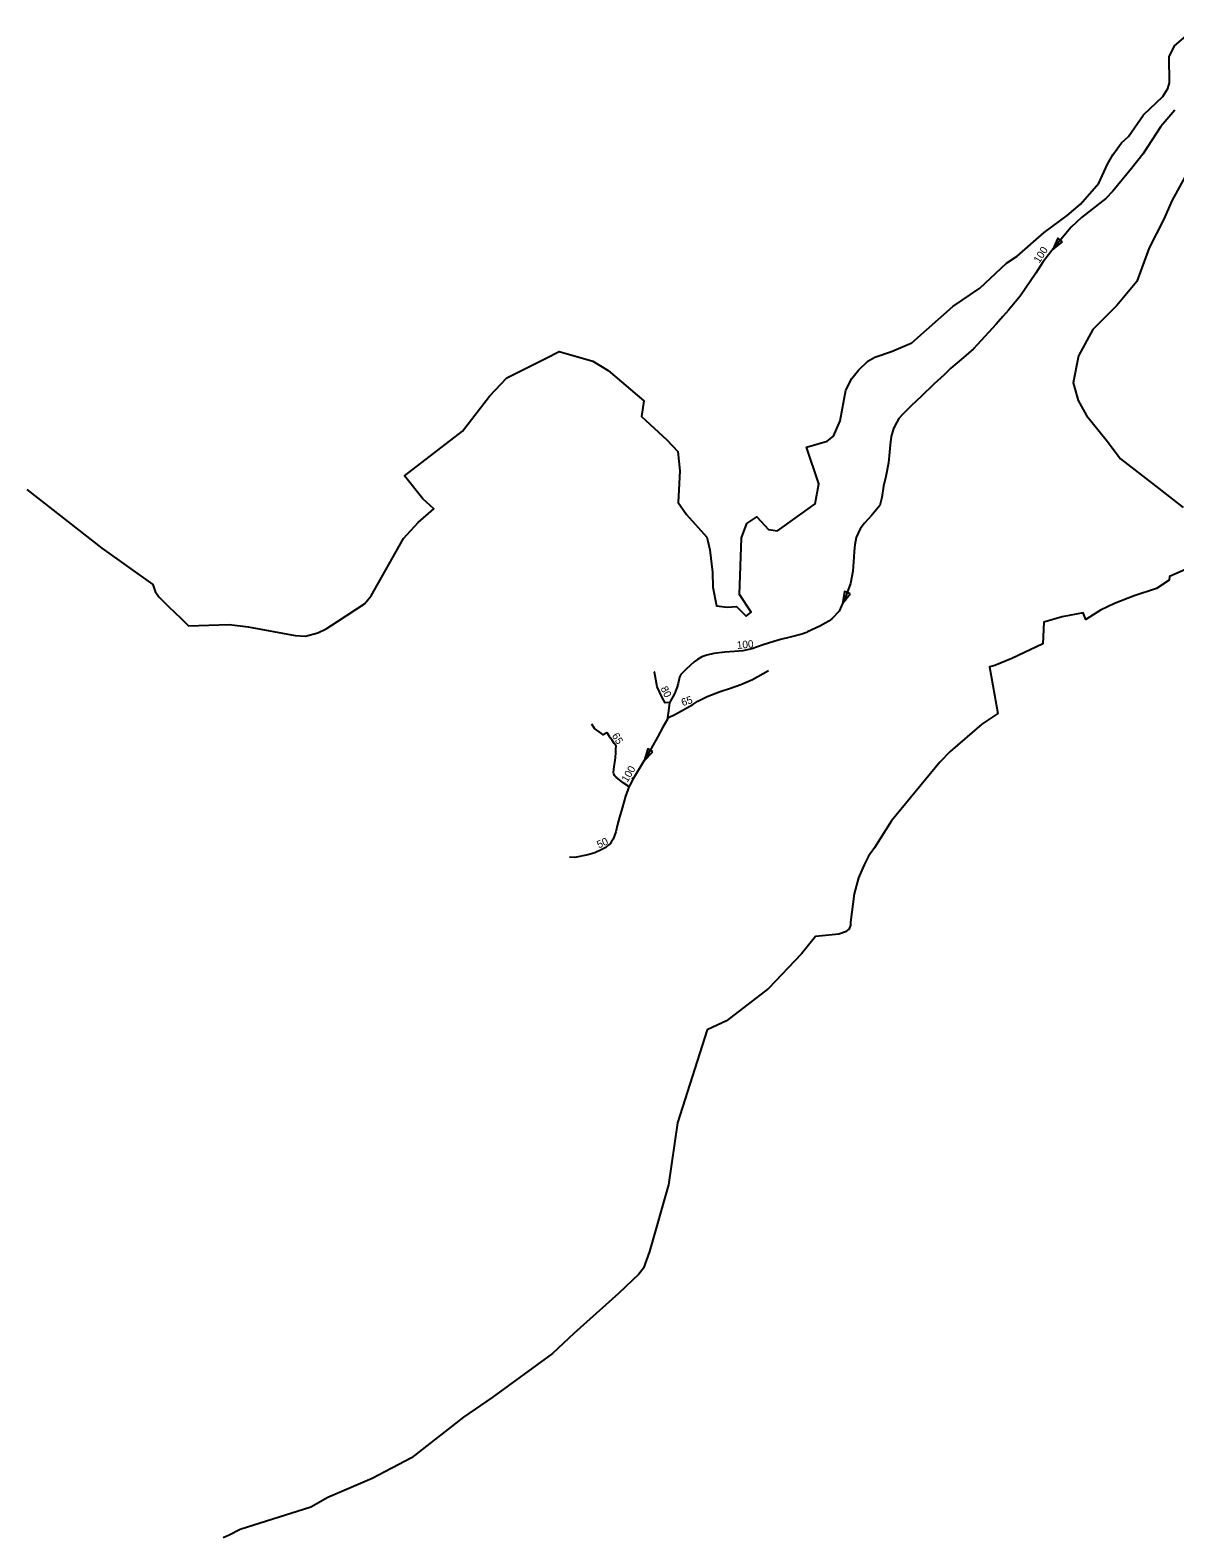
# Model space of a CAD drawing. Extents: x -547132 to -534149, y -1095664 to -1090118.
# Drawn here: x -545605 to -544078, y -1095664 to -1093653 of the extents above; entities that cross this region are included whole.
import ezdxf

# ---------------------------------------------------------------- set-up
doc = ezdxf.new("R2010")
doc.units = 0
doc.layers.add('Vrstva 3', color=7, linetype='Continuous')
doc.layers.add('Vrstva 54', color=7, linetype='Continuous')

msp = doc.modelspace()

# ---------------------------------------------------------------- linework, layer by layer
at = {"layer": 'Vrstva 3'}
for p, q in [((-544346.8, -1094078.5), (-544347, -1094078.4)), ((-544346.8, -1094078.5), (-544347, -1094078.4)), ((-544471.6, -1094287.4), (-544471.4, -1094287.4)), ((-544471.6, -1094287.4), (-544471.4, -1094287.4)), ((-544516.6, -1094407.1), (-544525.9, -1094428.4)), ((-544516.6, -1094407.1), (-544525.9, -1094428.4)), ((-544800.4, -1094652), (-544802.4, -1094650.8)), ((-544800.4, -1094652), (-544802.4, -1094650.8))]:
    msp.add_line(p, q, dxfattribs=at)
for points in [[(-544078.1, -1093759.8), (-544096.7, -1093782), (-544120.8, -1093818.9), (-544135.7, -1093837.7), (-544160.8, -1093868.2), (-544170, -1093877.9), (-544188.5, -1093891.9), (-544202.8, -1093903.2), (-544216.3, -1093916.1), (-544238.9, -1093943.2), (-544254, -1093962.7), (-544263.4, -1093977.3), (-544284.6, -1094008), (-544299.8, -1094026.6), (-544307.5, -1094035.3), (-544316.2, -1094045.5), (-544341.9, -1094072.9), (-544346.8, -1094078.5)], [(-544078.1, -1093759.8), (-544096.7, -1093782), (-544120.8, -1093818.9), (-544135.7, -1093837.7), (-544160.8, -1093868.2), (-544170, -1093877.9), (-544188.5, -1093891.9), (-544202.8, -1093903.2), (-544216.3, -1093916.1), (-544238.9, -1093943.2), (-544254, -1093962.7), (-544263.4, -1093977.3), (-544284.6, -1094008), (-544299.8, -1094026.6), (-544307.5, -1094035.3), (-544316.2, -1094045.5), (-544341.9, -1094072.9), (-544346.8, -1094078.5)], [(-544346.8, -1094078.5), (-544360, -1094090.1), (-544376.9, -1094104), (-544385.9, -1094112.9), (-544399.2, -1094125.1), (-544416.6, -1094141.7), (-544429.5, -1094154), (-544440.9, -1094165.4), (-544446.1, -1094171.2), (-544449, -1094176), (-544453.2, -1094184.5), (-544456.3, -1094195.3), (-544457.9, -1094206.5), (-544458.8, -1094216.1), (-544460.1, -1094230.3), (-544463.6, -1094248.7), (-544466.5, -1094261.6), (-544469, -1094276.7), (-544471.6, -1094287.4)], [(-544346.8, -1094078.5), (-544360, -1094090.1), (-544376.9, -1094104), (-544385.9, -1094112.9), (-544399.2, -1094125.1), (-544416.6, -1094141.7), (-544429.5, -1094154), (-544440.9, -1094165.4), (-544446.1, -1094171.2), (-544449, -1094176), (-544453.2, -1094184.5), (-544456.3, -1094195.3), (-544457.9, -1094206.5), (-544458.8, -1094216.1), (-544460.1, -1094230.3), (-544463.6, -1094248.7), (-544466.5, -1094261.6), (-544469, -1094276.7), (-544471.6, -1094287.4)], [(-544471.6, -1094287.4), (-544482.4, -1094300.3), (-544492.2, -1094310.9), (-544498, -1094318.5), (-544503, -1094330.1), (-544504.8, -1094339.7), (-544505.8, -1094348.2)], [(-544471.6, -1094287.4), (-544482.4, -1094300.3), (-544492.2, -1094310.9), (-544498, -1094318.5), (-544503, -1094330.1), (-544504.8, -1094339.7), (-544505.8, -1094348.2)], [(-544505.8, -1094348.2), (-544506.3, -1094356), (-544507.5, -1094374.7), (-544510.9, -1094391.5), (-544516.6, -1094407.1)], [(-544505.8, -1094348.2), (-544506.3, -1094356), (-544507.5, -1094374.7), (-544510.9, -1094391.5), (-544516.6, -1094407.1)], [(-544525.9, -1094428.4), (-544535.2, -1094438.1), (-544539.6, -1094441.5), (-544551.5, -1094448.4), (-544567.9, -1094455.9), (-544569.6, -1094456.6), (-544575.6, -1094458.8), (-544591, -1094463.1), (-544604, -1094465.9), (-544612.9, -1094468.6), (-544627.3, -1094473.1), (-544642.3, -1094478.5), (-544654.5, -1094481.1), (-544665.5, -1094482.1), (-544678.4, -1094482.8), (-544692.9, -1094484.9), (-544702.5, -1094487), (-544708.9, -1094489.3), (-544715, -1094492.6), (-544719.3, -1094495.7), (-544730.1, -1094505.5), (-544737.2, -1094512.7), (-544738.7, -1094516.4), (-544740.7, -1094524.8), (-544742.3, -1094530.6), (-544745.4, -1094538.3), (-544751.7, -1094549.5), (-544752, -1094550.3)], [(-544525.9, -1094428.4), (-544535.2, -1094438.1), (-544539.6, -1094441.5), (-544551.5, -1094448.4), (-544567.9, -1094455.9), (-544569.6, -1094456.6), (-544575.6, -1094458.8), (-544591, -1094463.1), (-544604, -1094465.9), (-544612.9, -1094468.6), (-544627.3, -1094473.1), (-544642.3, -1094478.5), (-544654.5, -1094481.1), (-544665.5, -1094482.1), (-544678.4, -1094482.8), (-544692.9, -1094484.9), (-544702.5, -1094487), (-544708.9, -1094489.3), (-544715, -1094492.6), (-544719.3, -1094495.7), (-544730.1, -1094505.5), (-544737.2, -1094512.7), (-544738.7, -1094516.4), (-544740.7, -1094524.8), (-544742.3, -1094530.6), (-544745.4, -1094538.3), (-544751.7, -1094549.5), (-544752, -1094550.3)], [(-544752, -1094550.3), (-544752.3, -1094550.2), (-544758.1, -1094550.7), (-544761.8, -1094543.3), (-544768.8, -1094529.1), (-544772.1, -1094509.6), (-544772, -1094509.4), (-544772.4, -1094509.3), (-544772.7, -1094509.3)], [(-544752, -1094550.3), (-544752.3, -1094550.2), (-544758.1, -1094550.7), (-544761.8, -1094543.3), (-544768.8, -1094529.1), (-544772.1, -1094509.6), (-544772, -1094509.4), (-544772.4, -1094509.3), (-544772.7, -1094509.3)], [(-544754.6, -1094570.7), (-544754.2, -1094570.7), (-544744.1, -1094565.7), (-544736.3, -1094561.2), (-544721.1, -1094552.8), (-544714.2, -1094548.1), (-544701.7, -1094542.1), (-544684.6, -1094535.5), (-544670.8, -1094530.8), (-544656.8, -1094526), (-544641.6, -1094519.4), (-544619.9, -1094507.4)], [(-544754.6, -1094570.7), (-544754.2, -1094570.7), (-544744.1, -1094565.7), (-544736.3, -1094561.2), (-544721.1, -1094552.8), (-544714.2, -1094548.1), (-544701.7, -1094542.1), (-544684.6, -1094535.5), (-544670.8, -1094530.8), (-544656.8, -1094526), (-544641.6, -1094519.4), (-544619.9, -1094507.4)], [(-544752, -1094550.3), (-544753.8, -1094564.4), (-544754.6, -1094570.7)], [(-544752, -1094550.3), (-544753.8, -1094564.4), (-544754.6, -1094570.7)], [(-544754.6, -1094570.7), (-544754.8, -1094572.2), (-544760.9, -1094583), (-544768, -1094596.3), (-544780.4, -1094618.6), (-544800.4, -1094652), (-544805.1, -1094660.5), (-544805.9, -1094662.3)], [(-544754.6, -1094570.7), (-544754.8, -1094572.2), (-544760.9, -1094583), (-544768, -1094596.3), (-544780.4, -1094618.6), (-544800.4, -1094652), (-544805.1, -1094660.5), (-544805.9, -1094662.3)], [(-544835.5, -1094590.4), (-544835.6, -1094590.5), (-544836.8, -1094591.1), (-544840.7, -1094593), (-544843, -1094591.2), (-544852.1, -1094584.6), (-544855.8, -1094579)], [(-544835.5, -1094590.4), (-544835.6, -1094590.5), (-544836.8, -1094591.1), (-544840.7, -1094593), (-544843, -1094591.2), (-544852.1, -1094584.6), (-544855.8, -1094579)], [(-544836.1, -1094589.7), (-544835.9, -1094589.9), (-544835.5, -1094590.4)], [(-544836.1, -1094589.7), (-544835.9, -1094589.9), (-544835.5, -1094590.4)], [(-544805.9, -1094662.3), (-544806.4, -1094662), (-544814, -1094657.2), (-544823.5, -1094649.7), (-544824.2, -1094649), (-544825.5, -1094647.2), (-544826.4, -1094645), (-544827, -1094643.6), (-544826.2, -1094639.1), (-544824.2, -1094623.7), (-544823.8, -1094616.9), (-544823.6, -1094612.7), (-544823.1, -1094608), (-544825.8, -1094604.6), (-544828.7, -1094600.3), (-544831.1, -1094597.1), (-544832.2, -1094595.3), (-544835.5, -1094590.4)], [(-544805.9, -1094662.3), (-544806.4, -1094662), (-544814, -1094657.2), (-544823.5, -1094649.7), (-544824.2, -1094649), (-544825.5, -1094647.2), (-544826.4, -1094645), (-544827, -1094643.6), (-544826.2, -1094639.1), (-544824.2, -1094623.7), (-544823.8, -1094616.9), (-544823.6, -1094612.7), (-544823.1, -1094608), (-544825.8, -1094604.6), (-544828.7, -1094600.3), (-544831.1, -1094597.1), (-544832.2, -1094595.3), (-544835.5, -1094590.4)], [(-544805.9, -1094662.3), (-544806.7, -1094663.9), (-544807.8, -1094666.6), (-544810.7, -1094674.9), (-544815.4, -1094690.8), (-544818.7, -1094703.2), (-544821.5, -1094712.8), (-544823.8, -1094722.7), (-544827.4, -1094732.3), (-544829.4, -1094735.4), (-544831.5, -1094738.5), (-544833.1, -1094740.1), (-544837.2, -1094743.5), (-544842.2, -1094746.2), (-544851.9, -1094750.4), (-544860.9, -1094753.2), (-544878.6, -1094756.7), (-544885.4, -1094756.5)], [(-544805.9, -1094662.3), (-544806.7, -1094663.9), (-544807.8, -1094666.6), (-544810.7, -1094674.9), (-544815.4, -1094690.8), (-544818.7, -1094703.2), (-544821.5, -1094712.8), (-544823.8, -1094722.7), (-544827.4, -1094732.3), (-544829.4, -1094735.4), (-544831.5, -1094738.5), (-544833.1, -1094740.1), (-544837.2, -1094743.5), (-544842.2, -1094746.2), (-544851.9, -1094750.4), (-544860.9, -1094753.2), (-544878.6, -1094756.7), (-544885.4, -1094756.5)]]:
    msp.add_lwpolyline(points, dxfattribs=at)
for points in [[(-544228, -1093935.5), (-544234.3, -1093930.6), (-544240.9, -1093945.7)], [(-544511.3, -1094405), (-544518.7, -1094401.8), (-544521.4, -1094418.1)], [(-544774.2, -1094616), (-544781.1, -1094611.9), (-544785.9, -1094627.7)]]:
    msp.add_lwpolyline(points, close=True, dxfattribs=at)
at = {"layer": 'Vrstva 54'}
for points in [[(-545609.5, -1094266.1), (-545509.4, -1094344.2), (-545441.3, -1094392.8), (-545438, -1094402.1), (-545433.4, -1094409), (-545420.6, -1094422.2), (-545403.6, -1094437.8), (-545393.6, -1094448), (-545339.3, -1094446.2), (-545314, -1094449.3), (-545251.5, -1094460.8), (-545237.9, -1094461.5), (-545221.4, -1094457.1), (-545210.2, -1094451.7), (-545195.1, -1094442.1), (-545159.2, -1094418.5), (-545150.3, -1094407.8), (-545106.9, -1094331.4), (-545087.6, -1094309.9), (-545066.3, -1094291.6), (-545081.1, -1094278.2), (-545105.6, -1094247.8), (-545028.1, -1094188.3), (-544992.1, -1094141.6), (-544969.3, -1094117.1), (-544916.7, -1094090.8), (-544899.3, -1094081.7), (-544854.6, -1094094.9), (-544833.8, -1094107.4), (-544786.2, -1094147.9), (-544789.5, -1094168.8), (-544755.7, -1094199.7), (-544741.2, -1094215.5), (-544738.5, -1094241), (-544740.6, -1094283.1), (-544729.6, -1094299.3), (-544702.4, -1094329.6), (-544701.1, -1094335), (-544698.4, -1094346.5), (-544694.8, -1094376.4), (-544694.5, -1094396.1), (-544689.5, -1094421.2), (-544675.4, -1094422.7), (-544662.8, -1094421.8), (-544649.8, -1094435), (-544643.1, -1094429.5), (-544658.9, -1094406.1), (-544656.3, -1094330.6), (-544648.9, -1094311.4), (-544635.7, -1094302.4), (-544620.3, -1094319.2), (-544608.3, -1094321), (-544557.7, -1094284.9), (-544552.9, -1094258.5), (-544569.2, -1094209.5), (-544541.9, -1094201.7), (-544533.3, -1094194.7), (-544524.5, -1094174.4), (-544517.1, -1094133.3), (-544509.1, -1094118.1), (-544500.2, -1094106.9), (-544487.4, -1094094.9), (-544478.2, -1094089.3), (-544456.1, -1094082), (-544429, -1094070.3), (-544374.2, -1094022.1), (-544338.2, -1093997.4), (-544302.7, -1093964), (-544288.3, -1093954.6), (-544252.6, -1093923), (-544221.5, -1093900.4), (-544203.8, -1093885.2), (-544179.6, -1093857.2), (-544167.7, -1093832.1), (-544160.9, -1093819.6), (-544149.2, -1093803.4), (-544140.1, -1093795.1), (-544120, -1093766.2), (-544094.3, -1093741.6), (-544087.4, -1093731.2), (-544085.3, -1093723.6), (-544085.5, -1093688.7), (-544078.6, -1093674), (-544054.1, -1093653.3)], [(-544064.2, -1093848.7), (-544082.3, -1093880.9), (-544092.7, -1093905.4), (-544112.5, -1093943.8), (-544128.9, -1093988.7), (-544155.5, -1094020.6), (-544187.3, -1094052.4), (-544206.6, -1094087.7), (-544213.7, -1094123.8), (-544207.2, -1094147.3), (-544196, -1094167.2), (-544169.8, -1094199.5), (-544150.7, -1094224.9), (-544107.3, -1094258.3), (-544067.1, -1094289.8)], [(-544056.6, -1094369.4), (-544085.4, -1094381.8), (-544085.8, -1094386.7), (-544102.4, -1094397.9), (-544132.2, -1094407.6), (-544158.6, -1094417.9), (-544177.1, -1094426.9), (-544196.7, -1094439.5), (-544200.4, -1094430.6), (-544228.4, -1094436), (-544252.8, -1094442.8), (-544254.3, -1094471.8), (-544295.6, -1094491.4), (-544318.2, -1094500.5), (-544325.4, -1094502.6), (-544314.4, -1094564.9), (-544335.7, -1094579.1), (-544377.6, -1094615.3), (-544391.6, -1094629.7), (-544456.2, -1094708.1), (-544478.9, -1094743.7), (-544486.6, -1094755.1), (-544492.5, -1094766.5), (-544500.2, -1094783.8), (-544505.8, -1094805.1), (-544510.7, -1094843.1), (-544510.9, -1094847.2), (-544512.5, -1094852), (-544517.6, -1094856.1), (-544526.3, -1094859), (-544557.6, -1094862.1), (-544575.9, -1094885.2), (-544620, -1094931.4), (-544676.1, -1094974.6), (-544701.8, -1094986.7), (-544741.3, -1095110.7), (-544753.3, -1095193.5), (-544778.7, -1095282.3), (-544786.9, -1095304.4), (-544793, -1095312.6), (-544820.2, -1095338.2), (-544879.6, -1095391.8), (-544908.3, -1095418.2), (-544988.8, -1095477), (-545027, -1095503.3), (-545096.2, -1095557.4), (-545148.7, -1095585.2), (-545208.1, -1095610.4), (-545230.7, -1095623.1), (-545325, -1095653), (-545339.6, -1095660.7), (-545347.3, -1095664.2)]]:
    msp.add_lwpolyline(points, dxfattribs=at)

# ---------------------------------------------------------------- texts
at = {"layer": 'Vrstva 3'}
for s, rotation, p in [('100', 57.2951, (-544258.9, -1093964.9)), ('100', 5.4013, (-544661.9, -1094478.7)), ('80', 296.2745, (-544764.4, -1094531.2)), ('65', 18.5632, (-544734.5, -1094555.1)), ('65', 301.0014, (-544829.4, -1094594.2)), ('100', 59.2214, (-544808.4, -1094657.4)), ('50', 23.3558, (-544846.5, -1094744.8))]:
    msp.add_text(s, height=10, rotation=rotation, dxfattribs=at).set_placement(p)

doc.saveas('drawing.dxf')
